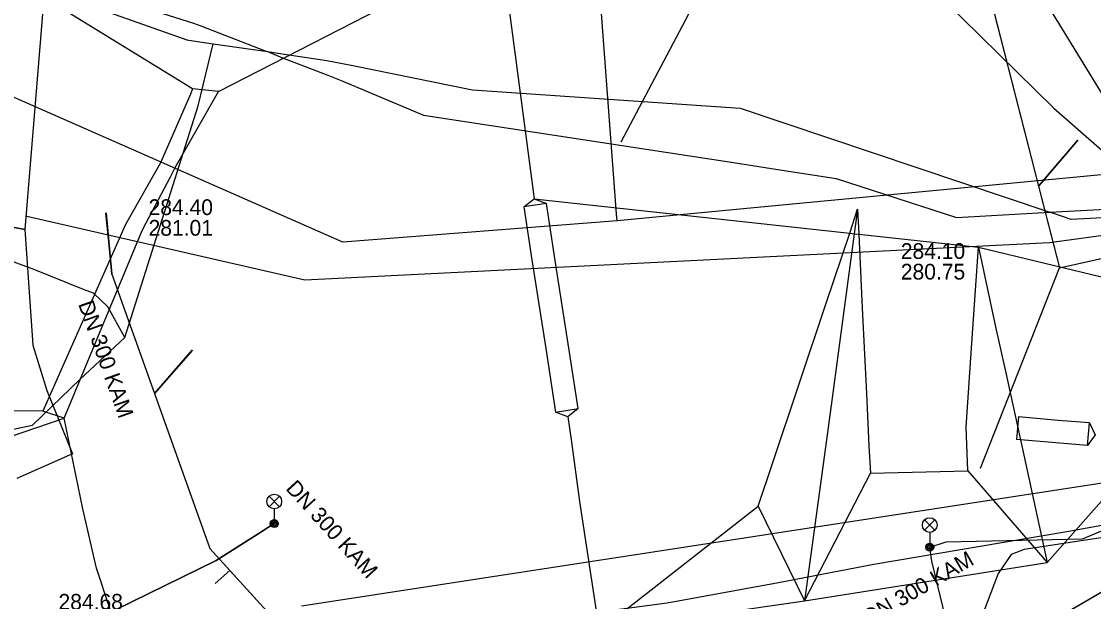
# Model space of a CAD drawing. Extents: x -599854 to -599675, y -1160809 to -1160543.
# Drawn here: x -599799.9 to -599745.4, y -1160620.8 to -1160591.3 of the extents above; entities that cross this region are included whole.
import ezdxf

# ---------------------------------------------------------------- set-up
doc = ezdxf.new("R2010")
doc.units = 0
for name, color, linetype in [('BKOM-ODVODNENI_trasa sítě', 7, 'Continuous'), ('BVK-KANALIZACE_ vyřazená trasa sítě', 7, 'Continuous'), ('BVK-VODOVOD_trasa zrušené sítě', 7, 'Continuous'), ('CETIN_kabel podzemní neprovozovaný', 7, 'Continuous'), ('DESTOVA-NEPROVOZOVANA_popisy', 7, 'Continuous'), ('DESTOVA_trasa neprovozované sítě', 7, 'Continuous'), ('DPMB_trolejové vedení-nosné lano', 7, 'Continuous'), ('DSP-JEDNOTNA-BVK_trasa sítě', 7, 'Continuous'), ('EON-NN_kabel zrušené sítě', 7, 'Continuous'), ('EON-VN_kabel', 7, 'Continuous'), ('EON-VN_kabel zrušené sítě', 7, 'Continuous'), ('TSB_kabel VO', 7, 'Continuous'), ('TSB_lampy VO', 7, 'Continuous')]:
    doc.layers.add(name, color=color, linetype=linetype)

msp = doc.modelspace()

# ---------------------------------------------------------------- linework, layer by layer
at = {"layer": 'BKOM-ODVODNENI_trasa sítě'}
for points in [[(-599752.61, -1160582.4), (-599748.203, -1160599.656), (-599748.115, -1160600), (-599747.14, -1160603.82)], [(-599746.21, -1160597.32), (-599748.203, -1160599.656)], [(-599747.14, -1160603.82), (-599728.85, -1160599.72)], [(-599795.632, -1160601.037), (-599795.3, -1160604.13)], [(-599795.3, -1160604.13), (-599793.14, -1160610.2), (-599790.33, -1160618.08)], [(-599751.15, -1160614.01), (-599747.14, -1160603.82)], [(-599791.206, -1160608.004), (-599793.14, -1160610.2)], [(-599760.76, -1160629.44), (-599734.15, -1160614)], [(-599790.33, -1160618.08), (-599781.73, -1160627.53)], [(-599790.053, -1160619.87), (-599789.314, -1160619.197)]]:
    msp.add_lwpolyline(points, dxfattribs=at)
at = {"layer": 'BVK-KANALIZACE_ vyřazená trasa sítě'}
for p, q in [((-599747.65, -1160602.53), (-599706.89, -1160596.87)), ((-599799.63, -1160601.195), (-599785.5, -1160604.42)), ((-599785.5, -1160604.42), (-599747.65, -1160602.53))]:
    msp.add_line(p, q, dxfattribs=at)
at = {"layer": 'BVK-VODOVOD_trasa zrušené sítě'}
msp.add_line((-599769.626, -1160601.428), (-599769.661, -1160601.069), dxfattribs=at)
for points in [[(-599769.661, -1160601.069), (-599773.22, -1160553.25), (-599773.248, -1160552.933), (-599773.31, -1160545.81)], [(-599769.626, -1160601.428), (-599783.571, -1160602.504), (-599806.4, -1160592.46)], [(-599723.722, -1160596.755), (-599729.139, -1160597.579), (-599769.626, -1160601.428)], [(-599679.2237, -1160599.5579), (-599732.933, -1160612.912), (-599785.657, -1160621.012)]]:
    msp.add_lwpolyline(points, dxfattribs=at)
at = {"layer": 'CETIN_kabel podzemní neprovozovaný'}
for points in [[(-599812.02, -1160583.41), (-599810.64, -1160583.64), (-599808.92, -1160584.27), (-599805.91, -1160586), (-599802.25, -1160587.71), (-599797.54, -1160589.34), (-599791.15, -1160591.37), (-599790.79, -1160591.51)], [(-599811.253, -1160583.779), (-599802.42, -1160588.03), (-599797.67, -1160590.02), (-599791.5, -1160592.22), (-599791.17, -1160592.27)], [(-599790.79, -1160591.51), (-599787.51, -1160592.78), (-599787.4, -1160592.82)], [(-599791.17, -1160592.27), (-599790.15, -1160592.42)], [(-599794.64, -1160607.36), (-599790.91, -1160595.58), (-599790.15, -1160592.42)], [(-599790.15, -1160592.42), (-599787.4, -1160592.82)], [(-599787.4, -1160592.82), (-599786.63, -1160593.13), (-599784.32, -1160594.02), (-599783.57, -1160594.33), (-599779.46, -1160596.05), (-599763.71, -1160598.46), (-599761.45, -1160598.81), (-599758.49, -1160599.27), (-599752.37, -1160601.26), (-599747.63, -1160600.99)], [(-599787.4, -1160592.82), (-599786.65, -1160592.94)], [(-599786.65, -1160592.94), (-599785.39, -1160593.12)], [(-599785.39, -1160593.12), (-599784.37, -1160593.27), (-599783.58, -1160593.43)], [(-599783.58, -1160593.43), (-599783.06, -1160593.53)], [(-599783.06, -1160593.53), (-599776.98, -1160594.76), (-599763.86, -1160595.66)], [(-599763.86, -1160595.66), (-599763.37, -1160595.69), (-599747.63, -1160600.99)], [(-599720.53, -1160598.22), (-599721.4, -1160598.46), (-599724.59, -1160599.37), (-599732.98, -1160600.73), (-599735.95, -1160600.85), (-599741.43, -1160601.08), (-599746.54, -1160601.36), (-599746.99, -1160601.21), (-599747.63, -1160600.99)], [(-599747.63, -1160600.99), (-599741.02, -1160600.62), (-599736.15, -1160600.06)], [(-599796.74, -1160604.91), (-599799.22, -1160603.92), (-599807.11, -1160601)], [(-599794.64, -1160607.36), (-599795.51, -1160605.8), (-599796.24, -1160605.11), (-599796.74, -1160604.91)], [(-599815.12, -1160614.04), (-599804.5, -1160612.89), (-599799.33, -1160611.82), (-599796.91, -1160609.47), (-599794.64, -1160607.36)]]:
    msp.add_lwpolyline(points, dxfattribs=at)
at = {"layer": 'DESTOVA-NEPROVOZOVANA_popisy'}
for p, q in [((-599793.438, -1160602.181), (-599793.438, -1160602.181)), ((-599755.201, -1160604.41), (-599755.201, -1160604.41))]:
    msp.add_line(p, q, dxfattribs=at)
at = {"layer": 'DESTOVA_trasa neprovozované sítě'}
for p, q in [((-599746.21, -1160597.32), (-599748.203, -1160599.656)), ((-599747.14, -1160603.82), (-599728.85, -1160599.72)), ((-599795.59, -1160601.02), (-599795.3, -1160604.13)), ((-599751.15, -1160614.01), (-599747.14, -1160603.82)), ((-599791.23, -1160608), (-599793.136, -1160610.205)), ((-599790.053, -1160619.87), (-599789.314, -1160619.197))]:
    msp.add_line(p, q, dxfattribs=at)
for points in [[(-599752.61, -1160582.4), (-599748.203, -1160599.656), (-599747.14, -1160603.82)], [(-599795.3, -1160604.13), (-599793.136, -1160610.205), (-599790.33, -1160618.08)], [(-599760.76, -1160629.44), (-599739.456, -1160617.079), (-599737.061, -1160615.689), (-599734.15, -1160614)], [(-599790.33, -1160618.08), (-599789.314, -1160619.197), (-599785.679, -1160623.191), (-599781.73, -1160627.53)]]:
    msp.add_lwpolyline(points, dxfattribs=at)
at = {"layer": 'DPMB_trolejové vedení-nosné lano'}
for points in [[(-599791.2, -1160594.72), (-599809.14, -1160583.7)], [(-599789.88, -1160594.84), (-599775.54, -1160587.47)], [(-599775.54, -1160587.47), (-599773.84, -1160600.3)], [(-599791.31, -1160594.98), (-599792.84, -1160598.48)], [(-599791.88, -1160598.36), (-599789.88, -1160594.84)], [(-599791.2, -1160594.72), (-599791.31, -1160594.98)], [(-599789.88, -1160594.84), (-599791.2, -1160594.72)], [(-599792.84, -1160598.48), (-599794.61, -1160601.61)], [(-599792.33, -1160599.19), (-599792.08, -1160598.72)], [(-599792.08, -1160598.72), (-599791.88, -1160598.36)], [(-599793.56, -1160601.53), (-599792.33, -1160599.19)], [(-599773.218, -1160600.54), (-599774.361, -1160600.716), (-599773.84, -1160600.3), (-599773.218, -1160600.54)], [(-599773.84, -1160600.3), (-599757.8, -1160602.05)], [(-599774.361, -1160600.716), (-599773.95, -1160603.4)], [(-599772.74, -1160603.67), (-599773.218, -1160600.54)], [(-599757.8, -1160602.05), (-599757.4, -1160600.84)], [(-599757.4, -1160600.84), (-599757.57, -1160602.08)], [(-599757.4, -1160600.84), (-599757.34, -1160602.1)], [(-599793.76, -1160601.91), (-599793.56, -1160601.53)], [(-599794.61, -1160601.61), (-599798.82, -1160611.1)], [(-599797.73, -1160611.46), (-599793.76, -1160601.91)], [(-599758.99, -1160605.61), (-599757.8, -1160602.05)], [(-599757.57, -1160602.08), (-599758.06, -1160605.74)], [(-599757.8, -1160602.05), (-599757.57, -1160602.08)], [(-599757.57, -1160602.08), (-599757.34, -1160602.1)], [(-599757.34, -1160602.1), (-599751.26, -1160602.76)], [(-599757.34, -1160602.1), (-599757.16, -1160605.87)], [(-599751.52, -1160606.66), (-599751.26, -1160602.76)], [(-599751.26, -1160602.76), (-599744.51, -1160604.39)], [(-599751.26, -1160602.76), (-599750.38, -1160606.82)], [(-599773.95, -1160603.4), (-599773.25, -1160607.92)], [(-599772.03, -1160608.23), (-599772.74, -1160603.67)], [(-599761.74, -1160613.81), (-599758.99, -1160605.61)], [(-599758.06, -1160605.74), (-599758.71, -1160610.56)], [(-599757.16, -1160605.87), (-599756.93, -1160610.54)], [(-599751.71, -1160609.39), (-599751.52, -1160606.66)], [(-599750.38, -1160606.82), (-599749.9, -1160609)], [(-599773.25, -1160607.92), (-599772.752, -1160611.15)], [(-599771.609, -1160610.974), (-599772.03, -1160608.23)], [(-599749.9, -1160609), (-599749.12, -1160612.56)], [(-599751.88, -1160611.92), (-599751.71, -1160609.39)], [(-599758.71, -1160610.56), (-599759.08, -1160613.3)], [(-599756.93, -1160610.54), (-599756.93, -1160610.57)], [(-599756.93, -1160610.57), (-599756.82, -1160612.87)], [(-599798.82, -1160611.1), (-599819.08, -1160611.06)], [(-599797.73, -1160611.46), (-599798.82, -1160611.1)], [(-599772.752, -1160611.15), (-599771.609, -1160610.974), (-599772.13, -1160611.39), (-599772.752, -1160611.15)], [(-599772.13, -1160611.39), (-599771.96, -1160612.55)], [(-599749.219, -1160611.396), (-599749.316, -1160612.548)], [(-599747.2, -1160611.57), (-599749.219, -1160611.396)], [(-599818.683, -1160618.617), (-599797.73, -1160611.46)], [(-599796.78, -1160616.07), (-599797.73, -1160611.46)], [(-599751.79, -1160614.13), (-599751.88, -1160611.92)], [(-599745.61, -1160611.702), (-599747.2, -1160611.57)], [(-599745.708, -1160612.854), (-599745.61, -1160611.702), (-599745.328, -1160612.306), (-599745.708, -1160612.854)], [(-599771.96, -1160612.55), (-599771.54, -1160615.69)], [(-599756.82, -1160612.87), (-599756.75, -1160614.25)], [(-599749.12, -1160612.56), (-599749.316, -1160612.548)], [(-599749.12, -1160612.56), (-599747.76, -1160618.8)], [(-599745.708, -1160612.854), (-599749.12, -1160612.56)], [(-599742.26, -1160612.57), (-599747.76, -1160618.8)], [(-599759.08, -1160613.3), (-599760.09, -1160620.75)], [(-599762.45, -1160615.93), (-599761.74, -1160613.81)], [(-599760.09, -1160620.75), (-599756.75, -1160614.25)], [(-599756.75, -1160614.25), (-599751.79, -1160614.13)], [(-599751.79, -1160614.13), (-599747.76, -1160618.8)], [(-599771.54, -1160615.69), (-599770.53, -1160622.26)], [(-599796.09, -1160619.09), (-599796.78, -1160616.07)], [(-599770.53, -1160622.26), (-599762.45, -1160615.93)], [(-599762.45, -1160615.93), (-599760.09, -1160620.75)], [(-599760.09, -1160620.75), (-599747.76, -1160618.8)], [(-599794.1, -1160625.09), (-599796.09, -1160619.09)], [(-599770.53, -1160622.26), (-599760.09, -1160620.75)]]:
    msp.add_lwpolyline(points, dxfattribs=at)
at = {"layer": 'DSP-JEDNOTNA-BVK_trasa sítě'}
for p, q in [((-599752.61, -1160582.4), (-599748.203, -1160599.656)), ((-599748.203, -1160599.656), (-599746.21, -1160597.32)), ((-599748.203, -1160599.656), (-599747.14, -1160603.82)), ((-599747.14, -1160603.82), (-599728.85, -1160599.72)), ((-599795.3, -1160604.13), (-599795.59, -1160601.02)), ((-599795.3, -1160604.13), (-599793.136, -1160610.205)), ((-599751.15, -1160614.01), (-599747.14, -1160603.82)), ((-599793.136, -1160610.205), (-599791.23, -1160608)), ((-599793.136, -1160610.205), (-599790.33, -1160618.08)), ((-599760.76, -1160629.44), (-599739.456, -1160617.079)), ((-599790.33, -1160618.08), (-599789.314, -1160619.197)), ((-599789.314, -1160619.197), (-599790.053, -1160619.87)), ((-599789.314, -1160619.197), (-599785.679, -1160623.191))]:
    msp.add_line(p, q, dxfattribs=at)
at = {"layer": 'EON-NN_kabel zrušené sítě'}
msp.add_lwpolyline([(-599761.266, -1160579.927), (-599762.197, -1160580.064), (-599762.963, -1160579.913), (-599762.99, -1160580.57), (-599760.74, -1160583.12), (-599756.91, -1160586.38), (-599752.09, -1160591.12), (-599747.43, -1160595.7), (-599744.03, -1160598.67)], dxfattribs=at)
at = {"layer": 'EON-VN_kabel'}
msp.add_lwpolyline([(-599743.23, -1160617.28), (-599748.93, -1160618.14), (-599749.59, -1160618.4), (-599750.25, -1160619.35), (-599750.99, -1160621.33), (-599751.35, -1160621.82), (-599752.03, -1160621.98), (-599752.78, -1160622.16), (-599760.56, -1160623.7), (-599765.25, -1160624.19), (-599772.02, -1160624.87), (-599778.24, -1160625.7), (-599785.33, -1160626.46), (-599788.97, -1160627.03), (-599794.53, -1160628.24), (-599797.86, -1160628.96), (-599803.25, -1160628.81), (-599809.12, -1160628.1), (-599814.22, -1160627.49), (-599816.61, -1160627.15), (-599817.41, -1160627.04)], dxfattribs=at)
at = {"layer": 'EON-VN_kabel zrušené sítě'}
msp.add_lwpolyline([(-599771.83, -1160621.47), (-599767.08, -1160620.85), (-599761.41, -1160619.81), (-599756.57, -1160618.89), (-599746.77, -1160617.22), (-599743.21, -1160616.58), (-599737.23, -1160615.44), (-599733.76, -1160614.74), (-599727.53, -1160613.39), (-599722.82, -1160612.38), (-599722.81, -1160612.35), (-599713.101, -1160609.819)], dxfattribs=at)
at = {"layer": 'TSB_kabel VO'}
for points in [[(-599766.71, -1160568.47), (-599766.89, -1160569.33), (-599774.64, -1160569.54), (-599774.72, -1160572.96), (-599776.23, -1160575.89), (-599779.31, -1160578.94), (-599785.83, -1160583.3), (-599790.5, -1160586.88), (-599791.37, -1160587.42), (-599791.05, -1160588.25), (-599794.55, -1160590.16), (-599798.76, -1160590.06), (-599799.72, -1160601.87), (-599800.78, -1160601.67)], [(-599766.71, -1160568.47), (-599762.32, -1160572.73), (-599758.16, -1160577.35), (-599760.07, -1160579.7), (-599764.277, -1160587.66), (-599769.44, -1160597.43)], [(-599712.85, -1160612.2), (-599713.231, -1160610.818), (-599715.05, -1160611.32), (-599720.13, -1160612.91), (-599729.8, -1160616.03), (-599730.26, -1160617.21), (-599734.33, -1160617.68), (-599739.29, -1160617.63), (-599739.48, -1160618.61), (-599740.14, -1160618.47), (-599744.95, -1160617.17), (-599744.01, -1160615.53), (-599741.64, -1160607.33), (-599740.03, -1160599.74), (-599742.84, -1160597.94), (-599743.59, -1160597.21), (-599749.46, -1160587.62), (-599756.62, -1160578.69), (-599758.16, -1160577.35), (-599762.32, -1160572.73), (-599766.71, -1160568.47)], [(-599800.78, -1160601.67), (-599799.72, -1160601.87), (-599799.32, -1160607.75), (-599798.61, -1160610.05), (-599797.31, -1160613.27), (-599800.14, -1160614.52)], [(-599796.01, -1160621.65), (-599790.01, -1160618.69), (-599787.68, -1160617.22), (-599787.05, -1160616.82), (-599787.68, -1160617.22), (-599790.01, -1160618.69), (-599796.01, -1160621.65)], [(-599752.78, -1160622.23), (-599753.62, -1160618.73), (-599753.73, -1160618.02), (-599752.89, -1160617.74), (-599745.97, -1160617.59), (-599744.95, -1160617.17)]]:
    msp.add_lwpolyline(points, dxfattribs=at)
at = {"layer": 'TSB_lampy VO'}
for p, q in [((-599787.315, -1160615.96), (-599786.785, -1160615.43)), ((-599787.315, -1160615.43), (-599786.785, -1160615.96)), ((-599787.315, -1160615.96), (-599786.785, -1160615.43)), ((-599787.315, -1160615.43), (-599786.785, -1160615.96)), ((-599787.05, -1160616.07), (-599787.05, -1160616.82)), ((-599787.05, -1160616.07), (-599787.05, -1160616.82)), ((-599753.995, -1160617.16), (-599753.465, -1160616.63)), ((-599753.995, -1160616.63), (-599753.465, -1160617.16)), ((-599753.995, -1160617.16), (-599753.465, -1160616.63)), ((-599753.995, -1160616.63), (-599753.465, -1160617.16)), ((-599753.73, -1160617.27), (-599753.73, -1160618.02)), ((-599753.73, -1160617.27), (-599753.73, -1160618.02))]:
    msp.add_line(p, q, dxfattribs=at)
for centre, radius in [((-599787.05, -1160615.695), 0.375), ((-599787.05, -1160615.695), 0.375), ((-599787.05, -1160616.82), 0.2), ((-599787.05, -1160616.82), 0.2), ((-599787.05, -1160616.82), 0.1445), ((-599787.05, -1160616.82), 0.1445), ((-599787.05, -1160616.82), 0.0876), ((-599787.05, -1160616.82), 0.0876), ((-599753.73, -1160616.895), 0.375), ((-599753.73, -1160616.895), 0.375), ((-599753.73, -1160618.02), 0.2), ((-599753.73, -1160618.02), 0.2), ((-599753.73, -1160618.02), 0.1445), ((-599753.73, -1160618.02), 0.1445), ((-599753.73, -1160618.02), 0.0876), ((-599753.73, -1160618.02), 0.0876)]:
    msp.add_circle(centre, radius, dxfattribs=at)

# ---------------------------------------------------------------- texts
at = {"layer": 'DESTOVA-NEPROVOZOVANA_popisy'}
for s, p in [('284.40', (-599793.438, -1160601.131)), ('281.01', (-599793.438, -1160602.181)), ('284.10', (-599755.201, -1160603.36)), ('280.75', (-599755.201, -1160604.41)), ('284.68', (-599798.016, -1160621.196))]:
    msp.add_text(s, height=0.8, dxfattribs=at).set_placement(p)
for rotation, p in [(289.60958, (-599797.026, -1160605.649)), (312.30385, (-599786.508, -1160615.062)), (30.12372, (-599756.81, -1160621.998))]:
    msp.add_text('DN 300 KAM', height=0.8, rotation=rotation, dxfattribs=at).set_placement(p)

doc.saveas('drawing.dxf')
